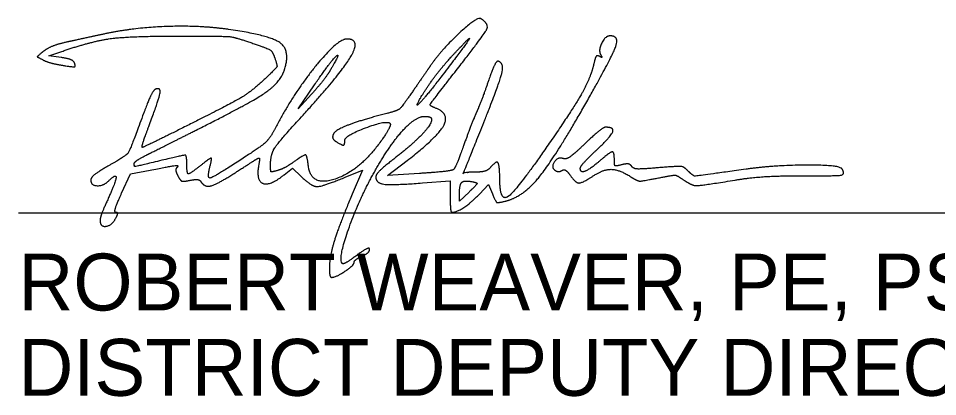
# Model space of a CAD drawing. Extents: x -21.1 to 50.3, y -4.9 to 22.1.
# Drawn here: x 24.752 to 27.013, y 1.846 to 2.776 of the extents above; entities that cross this region are included whole.
import ezdxf

# ---------------------------------------------------------------- set-up
doc = ezdxf.new("R2010")
doc.units = 0
doc.layers.add('SH_Data', color=7, linetype='Continuous')
doc.layers.add('SH_Text', color=7, linetype='Continuous')

msp = doc.modelspace()

# ---------------------------------------------------------------- linework, layer by layer
at = {"layer": 'SH_Data'}
msp.add_line((24.7523, 2.2975), (28.2523, 2.2975), dxfattribs=at)
at = {"layer": 'SH_Text'}
for points in [[(24.8574, 2.6801), (24.8275, 2.6841), (24.8542, 2.6934)], [(25.4731, 2.5899), (25.4405, 2.5542), (25.4807, 2.6131)], [(25.7389, 2.3947), (25.6599, 2.3896), (25.7085, 2.4268)], [(25.0062, 2.3464), (25.0277, 2.3938), (25.0762, 2.4031)], [(25.4061, 2.3914), (25.4266, 2.4075), (25.4475, 2.3875)], [(25.5558, 2.3854), (25.5983, 2.4029), (25.5734, 2.3438)], [(25.7459, 2.3713), (25.8142, 2.3764), (25.8142, 2.3377)], [(25.8861, 2.344), (25.9085, 2.3676), (25.9182, 2.3445)], [(25.8605, 2.349), (25.8371, 2.3266), (25.8371, 2.3473)]]:
    msp.add_lwpolyline(points, dxfattribs=at)
for points in [[(25.8896, 2.7756), (25.8807, 2.7812), (25.7933, 2.6997), (25.7658, 2.6601)], [(25.8151, 2.6304), (25.8967, 2.7349), (25.9109, 2.7625), (25.8896, 2.7756)], [(24.9609, 2.7375), (24.9336, 2.7316), (24.8934, 2.7228), (24.8714, 2.718)], [(25.2693, 2.7492), (25.1973, 2.7594), (25.0333, 2.7532), (24.9609, 2.7375)], [(25.407, 2.6507), (25.4219, 2.6976), (25.3696, 2.7349), (25.2693, 2.7492)], [(24.8714, 2.718), (24.8495, 2.7131), (24.824, 2.7031), (24.8147, 2.6956)], [(24.8542, 2.6934), (24.9324, 2.7205), (25.0269, 2.733), (25.1513, 2.7329)], [(25.1513, 2.7329), (25.2609, 2.7327), (25.2834, 2.7306), (25.3265, 2.7159)], [(25.3265, 2.7159), (25.3663, 2.7023), (25.3774, 2.6949), (25.3831, 2.6783)], [(25.56, 2.7255), (25.5367, 2.7252), (25.4265, 2.5882), (25.3855, 2.5085)], [(25.4523, 2.5384), (25.546, 2.641), (25.595, 2.726), (25.56, 2.7255)], [(25.8399, 2.7064), (25.8681, 2.7361), (25.8527, 2.7119), (25.7969, 2.639)], [(26.1524, 2.5754), (26.2122, 2.6813), (26.2305, 2.7333), (26.2078, 2.7333)], [(26.2078, 2.7333), (26.1953, 2.7333), (26.1778, 2.6971), (26.1848, 2.6858)], [(24.8147, 2.6956), (24.7984, 2.6824), (24.7983, 2.6818), (24.8128, 2.6742)], [(25.7504, 2.5953), (25.7686, 2.6239), (25.808, 2.6728), (25.8399, 2.7064)], [(24.8128, 2.6742), (24.8209, 2.67), (24.8425, 2.664), (24.8608, 2.6609)], [(24.8907, 2.6658), (24.8888, 2.6715), (24.8738, 2.6779), (24.8574, 2.6801)], [(25.3831, 2.6783), (25.3893, 2.6604), (25.3872, 2.6546), (25.3677, 2.6359)], [(25.4807, 2.6131), (25.5198, 2.6705), (25.5469, 2.6956), (25.5194, 2.649)], [(25.8993, 2.5266), (25.9361, 2.6191), (25.947, 2.6661), (25.9328, 2.6709)], [(25.9328, 2.6709), (25.9288, 2.6722), (25.9182, 2.6516), (25.9092, 2.6252)], [(26.1813, 2.6829), (26.176, 2.6861), (26.1709, 2.68), (26.168, 2.6669)], [(26.1848, 2.6858), (26.1878, 2.681), (26.1863, 2.6798), (26.1813, 2.6829)], [(24.8608, 2.6609), (24.8872, 2.6566), (24.8934, 2.6576), (24.8907, 2.6658)], [(25.1894, 2.5013), (25.3218, 2.5676), (25.397, 2.6193), (25.407, 2.6507)], [(25.5194, 2.649), (25.5118, 2.6362), (25.491, 2.6096), (25.4731, 2.5899)], [(25.7658, 2.6601), (25.7568, 2.6471), (25.7361, 2.6171), (25.7198, 2.5935)], [(26.168, 2.6669), (26.1602, 2.6318), (26.1199, 2.559), (26.0606, 2.473)], [(25.3677, 2.6359), (25.3292, 2.5992), (25.2807, 2.5692), (25.1686, 2.513)], [(25.7969, 2.639), (25.7504, 2.5783), (25.7239, 2.5533), (25.7504, 2.5953)], [(25.7764, 2.5564), (25.7631, 2.5614), (25.767, 2.5689), (25.8151, 2.6304)], [(25.9092, 2.6252), (25.9001, 2.5987), (25.8868, 2.5634), (25.8795, 2.5466)], [(25.0905, 2.6025), (25.0853, 2.6008), (25.0716, 2.5738), (25.0602, 2.5425)], [(25.073, 2.5104), (25.0975, 2.5754), (25.1034, 2.6068), (25.0905, 2.6025)], [(25.7198, 2.5935), (25.6954, 2.5581), (25.6846, 2.549), (25.6588, 2.5425)], [(25.7085, 2.4268), (25.7833, 2.4841), (25.8139, 2.5425), (25.7764, 2.5564)], [(25.9492, 2.3264), (25.9929, 2.3366), (26.0727, 2.4344), (26.1524, 2.5754)], [(25.0602, 2.5425), (25.0274, 2.4527), (25.0176, 2.4382), (24.9721, 2.4125)], [(25.3723, 2.4148), (25.3723, 2.4415), (25.3933, 2.4739), (25.4523, 2.5384)], [(25.6588, 2.5425), (25.5954, 2.5263), (25.5304, 2.5009), (25.5265, 2.4908)], [(25.6371, 2.4145), (25.6708, 2.4719), (25.7304, 2.5352), (25.7507, 2.5352)], [(25.7507, 2.5352), (25.7605, 2.5352), (25.7685, 2.5318), (25.7685, 2.5276)], [(25.8795, 2.5466), (25.8722, 2.5298), (25.8576, 2.4921), (25.847, 2.4628)], [(25.0572, 2.459), (25.0552, 2.459), (25.0624, 2.4821), (25.073, 2.5104)], [(25.1686, 2.513), (25.1092, 2.4833), (25.0591, 2.459), (25.0572, 2.459)], [(25.5552, 2.4768), (25.5552, 2.488), (25.6579, 2.5264), (25.666, 2.5183)], [(25.666, 2.5183), (25.6687, 2.5156), (25.6606, 2.4984), (25.648, 2.4801)], [(25.7685, 2.5276), (25.7685, 2.5154), (25.7184, 2.4633), (25.6731, 2.4284)], [(25.8775, 2.398), (25.8464, 2.398), (25.845, 2.3899), (25.8993, 2.5266)], [(25.0694, 2.4411), (25.0872, 2.45), (25.1412, 2.4771), (25.1894, 2.5013)], [(25.3855, 2.5085), (25.3713, 2.4809), (25.3472, 2.4594), (25.2863, 2.4201)], [(25.5265, 2.4908), (25.5243, 2.485), (25.5272, 2.4773), (25.5331, 2.4736)], [(26.1965, 2.5085), (26.1916, 2.5085), (26.1686, 2.4902), (26.1454, 2.4678)], [(26.1732, 2.4515), (26.2089, 2.485), (26.2185, 2.5085), (26.1965, 2.5085)], [(25.648, 2.4801), (25.5954, 2.4037), (25.4715, 2.3597), (25.4651, 2.4152)], [(25.5331, 2.4736), (25.5482, 2.464), (25.5552, 2.465), (25.5552, 2.4768)], [(26.0606, 2.473), (25.9785, 2.3537), (25.9361, 2.3229), (25.9361, 2.3823)], [(26.1454, 2.4678), (26.1197, 2.4429), (26.0989, 2.4287), (26.0922, 2.4313)], [(25.847, 2.4628), (25.8365, 2.4335), (25.8256, 2.4073), (25.8229, 2.4047)], [(26.1342, 2.4067), (26.1342, 2.4112), (26.1517, 2.4314), (26.1732, 2.4515)], [(26.218, 2.4277), (26.218, 2.4483), (26.2078, 2.448), (26.1832, 2.4266)], [(25.0371, 2.419), (25.0371, 2.4221), (25.0516, 2.4321), (25.0694, 2.4411)], [(25.0942, 2.4245), (25.0411, 2.4117), (25.0371, 2.4113), (25.0371, 2.419)], [(25.1666, 2.4171), (25.1666, 2.4395), (25.1593, 2.4403), (25.0942, 2.4245)], [(25.223, 2.4095), (25.2288, 2.4325), (25.2245, 2.4332), (25.1991, 2.4133)], [(25.2863, 2.4201), (25.2317, 2.3848), (25.2162, 2.3822), (25.223, 2.4095)], [(25.2854, 2.3965), (25.3101, 2.4124), (25.3342, 2.4278), (25.3388, 2.4306)], [(25.3388, 2.4306), (25.3444, 2.4339), (25.346, 2.4293), (25.3436, 2.4168)], [(25.4272, 2.4215), (25.4159, 2.4135), (25.3989, 2.4047), (25.3894, 2.402)], [(25.4651, 2.4152), (25.4623, 2.4399), (25.455, 2.4412), (25.4272, 2.4215)], [(25.6731, 2.4284), (25.6501, 2.4107), (25.6313, 2.3917), (25.6313, 2.3863)], [(25.9361, 2.3823), (25.9361, 2.416), (25.9273, 2.4264), (25.9132, 2.4094)], [(26.0922, 2.4313), (26.0789, 2.4364), (26.0614, 2.4091), (26.0732, 2.4018)], [(26.1832, 2.4266), (26.159, 2.4055), (26.1342, 2.3955), (26.1342, 2.4067)], [(26.2366, 2.4163), (26.2213, 2.4124), (26.218, 2.4145), (26.218, 2.4277)], [(24.9721, 2.4125), (24.9491, 2.3995), (24.9304, 2.3841), (24.9304, 2.3783)], [(25.0762, 2.4031), (25.1326, 2.4138), (25.1481, 2.4151), (25.1415, 2.4085)], [(25.1415, 2.4085), (25.1388, 2.4058), (25.1403, 2.3969), (25.1447, 2.3886)], [(25.1991, 2.4133), (25.1736, 2.3932), (25.1666, 2.394), (25.1666, 2.4171)], [(25.201, 2.3749), (25.2101, 2.3602), (25.2414, 2.3682), (25.2854, 2.3965)], [(25.3436, 2.4168), (25.3361, 2.3774), (25.3705, 2.3634), (25.4061, 2.3914)], [(25.3894, 2.402), (25.3751, 2.3978), (25.3723, 2.3999), (25.3723, 2.4148)], [(25.5491, 2.173), (25.5376, 2.1845), (25.5957, 2.3441), (25.6371, 2.4145)], [(25.8229, 2.4047), (25.8202, 2.4021), (25.7824, 2.3976), (25.7389, 2.3947)], [(25.9132, 2.4094), (25.908, 2.4031), (25.892, 2.398), (25.8775, 2.398)], [(26.0732, 2.4018), (26.0774, 2.3993), (26.0846, 2.3994), (26.0891, 2.4022)], [(26.0891, 2.4022), (26.0936, 2.405), (26.1024, 2.4001), (26.1086, 2.3912)], [(26.1677, 2.3898), (26.1921, 2.4059), (26.232, 2.4038), (26.2612, 2.3849)], [(26.2605, 2.4123), (26.2575, 2.4172), (26.2472, 2.4189), (26.2366, 2.4163)], [(26.3261, 2.4087), (26.2844, 2.4052), (26.2642, 2.4063), (26.2605, 2.4123)], [(26.3989, 2.4011), (26.3884, 2.4116), (26.3764, 2.4128), (26.3261, 2.4087)], [(26.5418, 2.4053), (26.4199, 2.3881), (26.4121, 2.3879), (26.3989, 2.4011)], [(26.7777, 2.4062), (26.7719, 2.4155), (26.61, 2.4149), (26.5418, 2.4053)], [(26.6725, 2.389), (26.764, 2.3886), (26.7863, 2.3923), (26.7777, 2.4062)], [(24.9304, 2.3783), (24.9304, 2.3652), (24.9619, 2.364), (24.9745, 2.3766)], [(24.9745, 2.3766), (24.9929, 2.395), (24.9923, 2.3748), (24.9731, 2.3328)], [(25.1447, 2.3886), (25.1509, 2.377), (25.1578, 2.3746), (25.1746, 2.3779)], [(25.1746, 2.3779), (25.1866, 2.3803), (25.1985, 2.379), (25.201, 2.3749)], [(25.4475, 2.3875), (25.4734, 2.3627), (25.4994, 2.3622), (25.5558, 2.3854)], [(25.6313, 2.3863), (25.6313, 2.3709), (25.6712, 2.3657), (25.7459, 2.3713)], [(25.8371, 2.3473), (25.8371, 2.3686), (25.8497, 2.3784), (25.8715, 2.3739)], [(25.8715, 2.3739), (25.8813, 2.3719), (25.8791, 2.3667), (25.8605, 2.349)], [(26.1086, 2.3912), (26.1225, 2.3714), (26.1391, 2.371), (26.1677, 2.3898)], [(26.2612, 2.3849), (26.2749, 2.3761), (26.2858, 2.3758), (26.3235, 2.3832)], [(26.3235, 2.3832), (26.3629, 2.3909), (26.3715, 2.3905), (26.3867, 2.3798)], [(26.3867, 2.3798), (26.408, 2.3649), (26.4311, 2.3647), (26.5152, 2.3786)], [(26.5152, 2.3786), (26.5508, 2.3845), (26.6216, 2.3891), (26.6725, 2.389)], [(24.9731, 2.3328), (24.9622, 2.309), (24.9532, 2.2848), (24.9532, 2.279)], [(24.9921, 2.299), (24.988, 2.299), (24.9943, 2.3203), (25.0062, 2.3464)], [(25.5734, 2.3438), (25.5413, 2.2678), (25.5171, 2.1891), (25.5171, 2.161)], [(25.8142, 2.3377), (25.8142, 2.3164), (25.8161, 2.299), (25.8184, 2.299)], [(25.8184, 2.299), (25.8299, 2.299), (25.8662, 2.3231), (25.8861, 2.344)], [(25.9182, 2.3445), (25.9267, 2.3244), (25.9307, 2.322), (25.9492, 2.3264)], [(24.9532, 2.279), (24.9532, 2.2629), (24.9821, 2.2665), (24.9913, 2.2837)], [(24.9913, 2.2837), (24.9964, 2.2931), (24.9966, 2.299), (24.9921, 2.299)], [(25.5843, 2.1931), (25.5667, 2.1802), (25.5509, 2.1711), (25.5491, 2.173)], [(25.6161, 2.208), (25.6161, 2.2127), (25.6018, 2.2059), (25.5843, 2.1931)], [(25.5971, 2.1909), (25.6075, 2.1957), (25.6161, 2.2034), (25.6161, 2.208)], [(25.5228, 2.139), (25.5329, 2.1391), (25.578, 2.169), (25.578, 2.1757)], [(25.578, 2.1757), (25.578, 2.1793), (25.5866, 2.1862), (25.5971, 2.1909)], [(25.5171, 2.161), (25.5171, 2.1489), (25.5196, 2.139), (25.5228, 2.139)]]:
    msp.add_open_spline(points, degree=2, dxfattribs=at)

# ---------------------------------------------------------------- texts
for s, p in [('ROBERT WEAVER, PE, PS', (24.7523, 2.0575)), ('DISTRICT DEPUTY DIRECTOR', (24.7523, 1.8475))]:
    msp.add_text(s, height=0.14, dxfattribs=at).set_placement(p)

doc.saveas('drawing.dxf')
